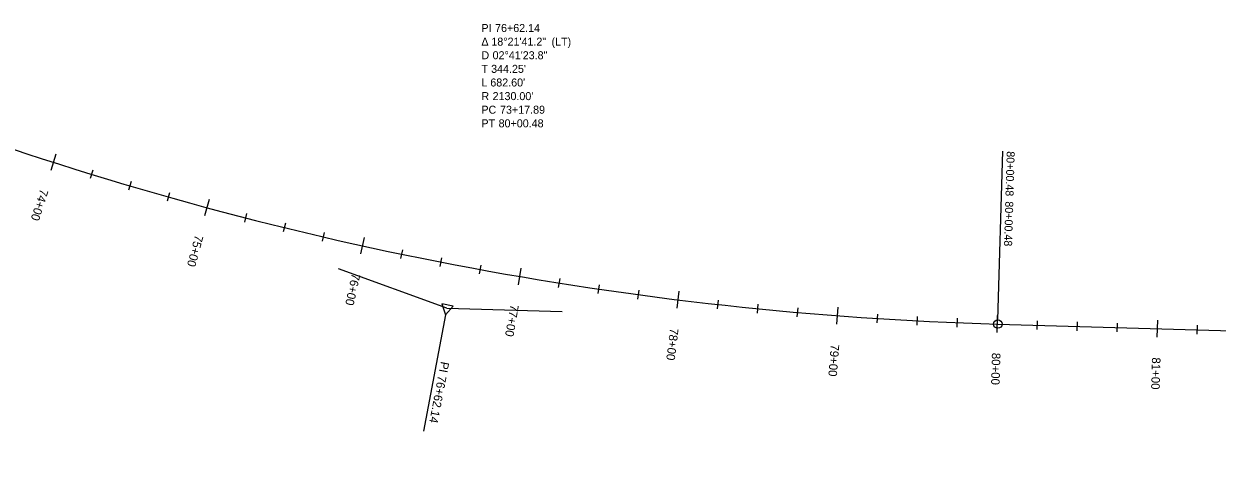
# Model space of a CAD drawing. Extents: x 2301963 to 2307911, y 760768 to 761974.
# Drawn here: x 2304184 to 2304930, y 760810 to 761086 of the extents above; entities that cross this region are included whole.
import ezdxf

# ---------------------------------------------------------------- set-up
doc = ezdxf.new("R2010")
doc.units = 0
for name, color, linetype in [('Default', 7, 'Continuous'), ('Draft_Curve Data Label', 7, 'Continuous'), ('Draft_Station Cardinal Lines', 7, 'Continuous'), ('Draft_Station Cardinal Points', 7, 'Continuous'), ('Draft_Station Labels Major', 7, 'Continuous'), ('Draft_Station Ticks Major', 7, 'Continuous'), ('Draft_Station Ticks Minor', 7, 'Continuous'), ('Geom_Secondary', 7, 'Continuous')]:
    doc.layers.add(name, color=color, linetype=linetype)

msp = doc.modelspace()

# ---------------------------------------------------------------- linework, layer by layer
at = {"layer": 'Default'}
msp.add_line((2304792.58, 760898.19), (2307901.31, 760809.5), dxfattribs=at)
msp.add_arc((2304853.32, 763027.32), 2130, 250.00439, 268.36584, dxfattribs=at)
at = {"layer": 'Draft_Station Cardinal Lines'}
for p, q in [((2304792.65, 760900.86), (2304795.66, 761006.15)), ((2304448.47, 760908.01), (2304380.81, 760932.63)), ((2304448.47, 760908.01), (2304520.44, 760905.95)), ((2304447.68, 760903.88), (2304433.83, 760831.39))]:
    msp.add_line(p, q, dxfattribs=at)
msp.add_lwpolyline([(2304447.69, 760903.92), (2304452.39, 760909.37), (2304445.32, 760910.72)], close=True, dxfattribs=at)
at = {"layer": 'Draft_Station Cardinal Points'}
for p, q in [((2304795.66, 761006.15), (2304795.66, 761006.15)), ((2304448.47, 760908.01), (2304448.47, 760908.01)), ((2304792.58, 760898.19), (2304792.58, 760898.19)), ((2304433.83, 760831.39), (2304433.83, 760831.39))]:
    msp.add_line(p, q, dxfattribs=at)
msp.add_circle((2304792.58, 760898.19), 2.67, dxfattribs=at)
at = {"layer": 'Draft_Station Ticks Major'}
for p, q in [((2304204.29, 761004.22), (2304201.04, 760994.11)), ((2304299.95, 760975.99), (2304297.18, 760965.74)), ((2304396.83, 760952.28), (2304394.55, 760941.91)), ((2304494.72, 760933.15), (2304492.92, 760922.68)), ((2304593.39, 760918.62), (2304592.09, 760908.08)), ((2304692.64, 760908.75), (2304691.84, 760898.16)), ((2304792.25, 760903.54), (2304791.94, 760892.93)), ((2304892.2, 760900.69), (2304891.9, 760890.07))]:
    msp.add_line(p, q, dxfattribs=at)
at = {"layer": 'Draft_Station Ticks Minor'}
for p, q in [((2304227.32, 760994.28), (2304225.69, 760989)), ((2304251.22, 760987.07), (2304249.66, 760981.78)), ((2304275.21, 760980.15), (2304273.71, 760974.83)), ((2304323.42, 760967.14), (2304322.04, 760961.8)), ((2304347.64, 760961.06), (2304346.32, 760955.7)), ((2304371.92, 760955.27), (2304370.67, 760949.89)), ((2304420.69, 760944.54), (2304419.57, 760939.14)), ((2304445.16, 760939.61), (2304444.11, 760934.19)), ((2304469.7, 760934.96), (2304468.7, 760929.53)), ((2304518.91, 760926.53), (2304518.05, 760921.08)), ((2304543.59, 760922.75), (2304542.79, 760917.29)), ((2304568.32, 760919.26), (2304567.58, 760913.79)), ((2304617.87, 760913.15), (2304617.26, 760907.67)), ((2304642.7, 760910.54), (2304642.16, 760905.04)), ((2304667.56, 760908.21), (2304667.08, 760902.71)), ((2304717.35, 760904.43), (2304717, 760898.93)), ((2304742.28, 760902.98), (2304741.99, 760897.47)), ((2304767.22, 760901.83), (2304767, 760896.31)), ((2304817.16, 760900.25), (2304817, 760894.73)), ((2304842.15, 760899.54), (2304841.99, 760894.02)), ((2304867.14, 760898.82), (2304866.98, 760893.31)), ((2304917.12, 760897.4), (2304916.96, 760891.88))]:
    msp.add_line(p, q, dxfattribs=at)
at = {"layer": 'Geom_Secondary'}
msp.add_line((2304792.58, 760898.19), (2307901.31, 760809.5), dxfattribs=at)
msp.add_arc((2304853.32, 763027.32), 2130, 250.00439, 268.36584, dxfattribs=at)

# ---------------------------------------------------------------- texts
at = {"layer": 'Draft_Curve Data Label'}
for s, p in [('PI ', (2304470.03, 761080.47)), ('76+62.14', (2304478.57, 761080.47)), ('Δ ', (2304470.03, 761071.97)), ('18°21\'41.2"', (2304476.25, 761071.97)), (' (LT)', (2304511.98, 761071.97)), ('D ', (2304470.03, 761063.47)), ('02°41\'23.8"', (2304477.02, 761063.47)), ('T ', (2304470.03, 761054.97)), ("344.25'", (2304476.11, 761054.97)), ('L ', (2304470.03, 761046.47)), ("682.60'", (2304475.6, 761046.47)), ('R ', (2304470.03, 761037.97)), ("2130.00'", (2304477.02, 761037.97)), ('PC ', (2304470.03, 761029.47)), ('73+17.89', (2304481.68, 761029.47)), ('PT ', (2304470.03, 761020.97)), ('80+00.48', (2304480.78, 761020.97))]:
    msp.add_text(s, height=5, dxfattribs=at).set_placement(p)
at = {"layer": 'Draft_Station Cardinal Points'}
for s, height, rotation, p in [('80+00.48', 5, 268.36584, (2304798.14, 761006.08)), ('80+00.48', 5, 268.36584, (2304797.25, 760974.83)), ('PI ', 5.34, 259.18512, (2304444.72, 760875.06)), ('76+62.14', 5.34, 259.18512, (2304443.05, 760866.31))]:
    msp.add_text(s, height=height, rotation=rotation, dxfattribs=at).set_placement(p)
at = {"layer": 'Draft_Station Labels Major'}
for s, rotation, p in [('74+00', 252.21315, (2304194.61, 760982.82)), ('75+00', 254.90309, (2304291.29, 760954.15)), ('76+00', 257.59303, (2304389.21, 760930.06)), ('77+00', 260.28297, (2304488.14, 760910.59)), ('78+00', 262.97292, (2304587.89, 760895.79)), ('79+00', 265.66286, (2304688.22, 760885.68)), ('80+00', 268.3528, (2304788.91, 760880.29)), ('81+00', 268.36584, (2304888.87, 760877.44))]:
    msp.add_text(s, height=5.34, rotation=rotation, dxfattribs=at).set_placement(p)

doc.saveas('drawing.dxf')
